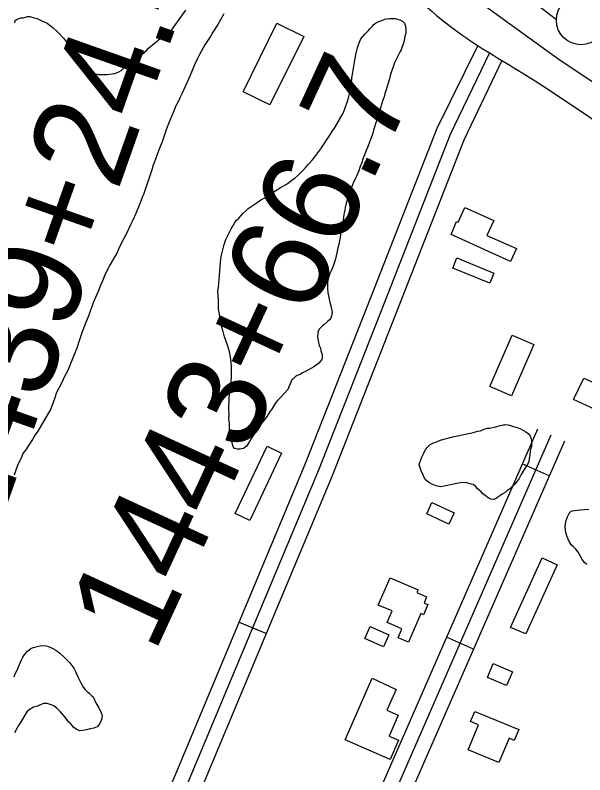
# Model space of a CAD drawing. Extents: x 3887375 to 3925618, y 296674 to 322633.
# Drawn here: x 3891643 to 3892222, y 311417 to 312189 of the extents above; entities that cross this region are included whole.
import ezdxf

# ---------------------------------------------------------------- set-up
doc = ezdxf.new("R2010")
doc.units = 0
for name, color, linetype in [('V-BLDG-OTLN', 7, 'Continuous'), ('V-LEVE-TOET', 7, 'Continuous'), ('V-RIVR-EDGE', 7, 'Continuous'), ('V-ROAD-CNTR', 7, 'Continuous'), ('V-RRAP-FSHR', 7, 'Continuous'), ('V-SITE-VEGE', 7, 'Continuous'), ('V-SURV-IDEN', 7, 'Continuous'), ('V-SURV-LINE', 7, 'Continuous')]:
    doc.layers.add(name, color=color, linetype=linetype)

msp = doc.modelspace()

# ---------------------------------------------------------------- linework, layer by layer
at = {"layer": 'V-BLDG-OTLN'}
for points in [[(3891902.41, 312097.6), (3891875.15, 312110.99), (3891909.54, 312180.64), (3891936.77, 312167.2)], [(3892086.66, 311965.84), (3892091.99, 311979.05), (3892093.66, 311978.3), (3892100.46, 311993.38), (3892129.87, 311980.1), (3892123.03, 311964.96), (3892152.89, 311951.48), (3892147.06, 311938.57)], [(3892092.51, 311942.05), (3892130.07, 311926.68), (3892125.81, 311916.29), (3892088.41, 311931.6)], [(3892148.62, 311863.4), (3892170.71, 311853.97), (3892148.11, 311801.7), (3892126.05, 311811.24)], [(3892221.56, 311819.8), (3892247.45, 311807.8), (3892237.28, 311785.86), (3892210.85, 311798.12)], [(3891899.55, 311750.87), (3891914.06, 311743.49), (3891881.89, 311675.27), (3891867.17, 311682.22)], [(3892067.12, 311693.45), (3892089.7, 311683.01), (3892084.36, 311671.47), (3892061.71, 311681.94)], [(3892147.02, 311566.42), (3892179.21, 311637.1), (3892194.4, 311630.18), (3892162.49, 311560.12)], [(3892024.54, 311617.05), (3892052.91, 311604.81), (3892051.63, 311601.83), (3892061.7, 311597.48), (3892059.01, 311591.25), (3892062.77, 311589.62), (3892058.35, 311579.37), (3892055.71, 311580.51), (3892043.16, 311551.43), (3892032.63, 311555.97), (3892036.59, 311565.15), (3892021.61, 311571.62), (3892026.6, 311583.18), (3892012.56, 311589.23)], [(3892004.29, 311567.43), (3892023.14, 311558.95), (3892017.7, 311546.85), (3891998.86, 311555.33)], [(3892129.22, 311529.73), (3892149, 311521.26), (3892143.03, 311507.34), (3892123.58, 311515.67)], [(3892006.17, 311515), (3892030.58, 311503.54), (3892021.31, 311482.29), (3892032.8, 311477.28), (3892023.54, 311456.06), (3892032.98, 311451.95), (3892024.46, 311432.39), (3891978.82, 311452.3)], [(3892110.7, 311481.05), (3892155.37, 311462.57), (3892150.83, 311451.61), (3892145.46, 311453.83), (3892135.23, 311429.12), (3892103.97, 311442.06), (3892114.44, 311467.37), (3892106.39, 311470.7)]]:
    msp.add_lwpolyline(points, close=True, dxfattribs=at)
at = {"layer": 'V-LEVE-TOET'}
msp.add_lwpolyline([(3891470.84, 312662.89), (3891560.54, 312610.95), (3891672.72, 312538.88), (3891789.15, 312457.06), (3891908.44, 312364.28), (3891989.87, 312296.2), (3892058.03, 312243.98), (3892194.92, 312144.74), (3892319.54, 312061.78), (3892457.42, 311963.54), (3892587.1, 311868.44), (3892728.16, 311772.22), (3892868.41, 311677.19), (3892941.75, 311626.8), (3893041.76, 311554.85), (3893157.21, 311470.62), (3893331.95, 311347.69), (3893386.65, 311309.75), (3893477.31, 311234.74), (3893652.21, 311086.68), (3893804.29, 310952.63), (3893919.11, 310842.87), (3893996.64, 310761.99)], dxfattribs=at)
at = {"layer": 'V-RIVR-EDGE'}
msp.add_spline([(3891467.98, 312833.96), (3891486.98, 312822.05), (3891534.01, 312792.8), (3891594.13, 312753.8), (3891650.38, 312718.69), (3891687.23, 312694.81), (3891715.84, 312678.71), (3891775.97, 312641.17), (3891829.3, 312607.04), (3891872.45, 312576.34), (3891897.65, 312554.91), (3891920.44, 312540.28), (3891948.54, 312515.93), (3892002.83, 312474.52), (3892042.08, 312440.43), (3892073.59, 312415.58), (3892102.19, 312395.6), (3892133.21, 312371.24), (3892200.11, 312321.54), (3892242.77, 312292.79), (3892291.73, 312258.18), (3892341.66, 312219.21), (3892369.29, 312198.26), (3892390.13, 312181.21), (3892413.88, 312163.18), (3892453.63, 312136.38), (3892487.09, 312113.47), (3892521.99, 312087.64), (3892554.96, 312065.22), (3892591.32, 312042.31), (3892628.16, 312015.99), (3892662.1, 311994.06), (3892686.84, 311979.91), (3892764.9, 311931.15), (3892805.14, 311902.89), (3892836.17, 311880.47), (3892877.86, 311852.69), (3892924.41, 311821.49), (3892965.13, 311793.23), (3893024.77, 311754.23), (3893079.06, 311715.73), (3893108.15, 311694.29), (3893146.45, 311668.94), (3893184.74, 311638.74), (3893227.88, 311606.09), (3893285.08, 311562.73), (3893338.89, 311523.75), (3893381.55, 311493.05), (3893441.66, 311449.68), (3893482.38, 311419.95), (3893505.63, 311395.61), (3893524.53, 311379.05), (3893555.07, 311358.1), (3893588.51, 311330.33), (3893620.5, 311305.49), (3893676.23, 311256.3), (3893730.02, 311212.46), (3893771.69, 311174.96), (3893804.16, 311145.26), (3893965.04, 311005.48), (3893991.69, 310979.19), (3894015.41, 310950.48), (3894041.09, 310924.19), (3894068.7, 310897.9)], degree=3, dxfattribs=at)
at = {"layer": 'V-ROAD-CNTR'}
for p, q in [((3892186.32, 311720.71), (3892158.83, 311732.72)), ((3891871.15, 311571.72), (3891898.83, 311560.14)), ((3892109.33, 311544.46), (3892081.84, 311556.47))]:
    msp.add_line(p, q, dxfattribs=at)
for points in [[(3891686.27, 311129.7), (3891938.31, 311732.3), (3892005.6, 311903.59), (3892072.28, 312073.95), (3892114.12, 312158.17)], [(3891700.11, 311123.91), (3891952.22, 311726.66), (3892019.56, 311898.11), (3892086.04, 312067.96), (3892125.89, 312150.89)], [(3891713.95, 311118.12), (3891966.12, 311721.03), (3892033.53, 311892.64), (3892099.8, 312061.97), (3892138.54, 312143.08)], [(3892174.23, 311767.97), (3892020.24, 311415.46), (3891893.42, 311123.43), (3891858.77, 311046.87)], [(3892187.97, 311761.96), (3892034, 311409.47), (3891907.14, 311117.35), (3891872.44, 311040.68)], [(3892201.72, 311755.96), (3892047.75, 311403.48), (3891920.85, 311111.27), (3891886.11, 311034.5)]]:
    msp.add_lwpolyline(points, dxfattribs=at)
for points in [[(3891930.71, 312305.17), (3892016.94, 312237.42), (3892090.97, 312173.45), (3892154.3, 312132.93), (3892292.49, 312039.88), (3892440.64, 311937.24), (3892591.28, 311832.93), (3892771.43, 311706.32), (3892952.89, 311582.91), (3893068.84, 311500.71)], [(3892116.12, 310915.27), (3892145.02, 310967.97), (3892195.12, 311066.62), (3892242.62, 311173.92), (3892293.84, 311292.92), (3892337.19, 311399.23), (3892384.83, 311516.5)]]:
    msp.add_spline(points, degree=3, dxfattribs=at)
at = {"layer": 'V-RRAP-FSHR'}
msp.add_spline([(3893114.78, 311697.57), (3893051.01, 311741.57), (3892934.52, 311826.93), (3892830.41, 311900.74), (3892716.58, 311970.79), (3892537.08, 312088.03), (3892396.96, 312185.57), (3892228.16, 312311.27), (3892082.04, 312421.65), (3891952.19, 312519.08)], degree=3, dxfattribs=at)
at = {"layer": 'V-SITE-VEGE'}
for p, q in [((3891801.48, 312172.66), (3891816.94, 312193.9)), ((3891645.23, 312184.85), (3891649.18, 312185.93)), ((3891649.18, 312185.93), (3891651.82, 312186.21)), ((3891651.82, 312186.21), (3891656.04, 312187.3)), ((3891656.04, 312187.3), (3891658.42, 312187.31)), ((3891658.42, 312187.31), (3891662.66, 312186.02)), ((3891662.66, 312186.02), (3891665.57, 312185.51)), ((3891665.57, 312185.51), (3891670.61, 312182.9)), ((3891855.54, 312190.19), (3891849.27, 312179.31)), ((3891642.87, 312181.13), (3891643.38, 312183.51)), ((3891643.38, 312183.51), (3891645.23, 312184.85)), ((3891670.61, 312182.9), (3891672.73, 312182.12)), ((3891672.73, 312182.12), (3891675.91, 312180.55)), ((3891675.91, 312180.55), (3891682.02, 312175.84)), ((3891849.27, 312179.31), (3891844.3, 312171.35)), ((3891682.02, 312175.84), (3891684.94, 312173.21)), ((3891684.94, 312173.21), (3891687.33, 312170.85)), ((3891687.33, 312170.85), (3891692.39, 312165.34)), ((3891797.54, 312169.72), (3891801.48, 312172.66)), ((3891844.3, 312171.35), (3891842.21, 312167.64)), ((3891692.39, 312165.34), (3891699.59, 312155.87)), ((3891778.87, 312155.07), (3891792.8, 312166.79)), ((3891792.8, 312166.79), (3891794.64, 312168.12)), ((3891794.64, 312168.12), (3891797.54, 312169.72)), ((3891842.21, 312167.64), (3891836.19, 312158.61)), ((3891699.59, 312155.87), (3891703.05, 312151.66)), ((3891777.03, 312152.94), (3891778.87, 312155.07)), ((3891836.19, 312158.61), (3891830.71, 312148.8)), ((3891703.05, 312151.66), (3891712.63, 312140.89)), ((3891765.47, 312144.14), (3891772.57, 312149.21)), ((3891772.57, 312149.21), (3891777.03, 312152.94)), ((3891830.71, 312148.8), (3891828.62, 312144.82)), ((3891712.63, 312140.89), (3891714.5, 312137.99)), ((3891755.73, 312136.94), (3891762.84, 312141.75)), ((3891762.84, 312141.75), (3891765.47, 312144.14)), ((3891828.62, 312144.82), (3891825.76, 312138.2)), ((3891714.5, 312137.99), (3891717.7, 312134.32)), ((3891717.7, 312134.32), (3891721.69, 312130.38)), ((3891748.64, 312131.08), (3891751.01, 312132.69)), ((3891751.01, 312132.69), (3891752.58, 312134.02)), ((3891752.58, 312134.02), (3891755.73, 312136.94)), ((3891825.76, 312138.2), (3891821.07, 312126.8)), ((3891721.69, 312130.38), (3891724.87, 312129.08)), ((3891724.87, 312129.08), (3891728.57, 312128.57)), ((3891728.57, 312128.57), (3891731.22, 312128.33)), ((3891731.22, 312128.33), (3891737.03, 312128.36)), ((3891737.03, 312128.36), (3891739.41, 312128.65)), ((3891739.41, 312128.65), (3891744.69, 312129.47)), ((3891744.69, 312129.47), (3891748.64, 312131.08)), ((3891821.07, 312126.8), (3891816.65, 312116.99)), ((3891816.65, 312116.99), (3891812.74, 312108.78)), ((3891812.74, 312108.78), (3891811.17, 312105.33)), ((3891809.87, 312102.15), (3891806.74, 312096.58)), ((3891811.17, 312105.33), (3891809.87, 312102.15)), ((3891806.74, 312096.58), (3891804.92, 312092.34)), ((3891804.92, 312092.34), (3891798.94, 312077.5)), ((3891798.94, 312077.5), (3891796.85, 312072.2)), ((3891796.85, 312072.2), (3891792.71, 312060.02)), ((3891792.71, 312060.02), (3891789.07, 312051.01)), ((3891789.07, 312051.01), (3891787.25, 312045.98)), ((3891784.65, 312038.83), (3891783.35, 312035.65)), ((3891786.21, 312043.6), (3891784.65, 312038.83)), ((3891787.25, 312045.98), (3891786.21, 312043.6)), ((3891782.58, 312032.47), (3891779.73, 312023.47)), ((3891783.35, 312035.65), (3891782.58, 312032.47)), ((3891779.73, 312023.47), (3891773.77, 312006.52)), ((3891772.72, 312004.4), (3891770.38, 311998.04)), ((3891773.77, 312006.52), (3891772.72, 312004.4)), ((3891770.38, 311998.04), (3891765.96, 311987.17)), ((3891765.96, 311987.17), (3891762.84, 311980.28)), ((3891762.84, 311980.28), (3891760.49, 311975.51)), ((3891760.49, 311975.51), (3891756.84, 311967.56)), ((3891753.97, 311961.73), (3891749.54, 311953.24)), ((3891756.84, 311967.56), (3891753.97, 311961.73)), ((3891746.93, 311947.67), (3891739.88, 311935.21)), ((3891749.54, 311953.24), (3891746.93, 311947.67)), ((3891739.88, 311935.21), (3891736.22, 311928.31)), ((3891734.14, 311923.81), (3891732.32, 311919.3)), ((3891736.22, 311928.31), (3891734.14, 311923.81)), ((3891732.32, 311919.3), (3891729.71, 311913.47)), ((3891728.42, 311909.76), (3891722.69, 311896.25)), ((3891729.71, 311913.47), (3891728.42, 311909.76)), ((3891722.69, 311896.25), (3891717.5, 311882.21)), ((3891717.5, 311882.21), (3891714.9, 311875.85)), ((3891713.6, 311871.88), (3891711.52, 311866.84)), ((3891714.9, 311875.85), (3891713.6, 311871.88)), ((3891711.52, 311866.84), (3891708.15, 311856.78)), ((3891708.15, 311856.78), (3891706.08, 311850.16)), ((3891704.25, 311846.18), (3891696.45, 311827.1)), ((3891706.08, 311850.16), (3891704.25, 311846.18)), ((3891696.45, 311827.1), (3891693.84, 311822.06)), ((3891690.45, 311814.91), (3891685.5, 311805.1)), ((3891693.84, 311822.06), (3891690.45, 311814.91)), ((3891685.5, 311805.1), (3891683.42, 311798.74)), ((3891681.86, 311795.03), (3891679.52, 311788.68)), ((3891683.42, 311798.74), (3891681.86, 311795.03)), ((3891679.52, 311788.68), (3891666.46, 311765.86)), ((3891663.58, 311762.14), (3891660.96, 311757.63)), ((3891666.46, 311765.86), (3891663.58, 311762.14)), ((3891660.96, 311757.63), (3891657.04, 311751.53)), ((3891654.95, 311748.08), (3891652.59, 311744.89)), ((3891657.04, 311751.53), (3891654.95, 311748.08)), ((3891649.72, 311739.33), (3891648.42, 311736.94)), ((3891651.28, 311743.3), (3891649.72, 311739.33)), ((3891652.59, 311744.89), (3891651.28, 311743.3)), ((3891645.81, 311731.11), (3891644.51, 311727.4)), ((3891648.42, 311736.94), (3891645.81, 311731.11)), ((3891644.51, 311727.4), (3891642.18, 311721.31))]:
    msp.add_line(p, q, dxfattribs=at)
for points in [[(3891861.49, 311765.02), (3891861.21, 311767.93), (3891861.17, 311774.53), (3891860.62, 311777.7), (3891860.84, 311783.52), (3891860.55, 311788.27), (3891861, 311799.9), (3891861.49, 311805.46), (3891862.76, 311813.39), (3891863.01, 311816.3), (3891863.24, 311821.06), (3891863.18, 311830.57), (3891862.88, 311836.12), (3891862.04, 311843.51), (3891861.22, 311846.94), (3891859.6, 311852.22), (3891857.45, 311858.02), (3891856.1, 311861.97), (3891854.75, 311867.25), (3891852.85, 311873.84), (3891850.93, 311884.93), (3891850.1, 311890.21), (3891850.05, 311898.67), (3891849.46, 311908.44), (3891849.96, 311912.14), (3891850.94, 311924.3), (3891852.17, 311937.79), (3891852.93, 311943.35), (3891855.76, 311955.52), (3891857.57, 311960.82), (3891863.05, 311971.69), (3891865.15, 311974.87), (3891866.45, 311977.26), (3891868.54, 311980.44), (3891870.65, 311982.31), (3891873, 311985.23), (3891874.84, 311987.09), (3891877.99, 311989.75), (3891880.36, 311992.15), (3891882.2, 311993.75), (3891890.36, 311999.09), (3891893.25, 312001.22), (3891896.41, 312002.83), (3891901.68, 312005.77), (3891905.09, 312008.43), (3891910.09, 312011.64), (3891913.25, 312013.51), (3891918.26, 312016.18), (3891921.41, 312018.31), (3891925.1, 312021.25), (3891927.72, 312023.11), (3891930.88, 312025.78), (3891936.65, 312031.63), (3891939.28, 312034.55), (3891941.64, 312037.48), (3891945.57, 312041.73), (3891947.93, 312044.65), (3891954.22, 312052.89), (3891957.62, 312057.93), (3891959.98, 312061.64), (3891963.11, 312066.95), (3891966.25, 312071.46), (3891968.09, 312073.85), (3891976.97, 312089.23), (3891978.27, 312092.42), (3891981.9, 312103.28), (3891983.96, 312111.48), (3891985.23, 312119.95), (3891985.73, 312124.44), (3891987.76, 312136.88), (3891988.26, 312140.84), (3891989.03, 312144.81), (3891989.53, 312148.52), (3891990.83, 312153.02), (3891991.34, 312155.66), (3891992.63, 312159.63), (3891994.71, 312164.67), (3891999.17, 312169.72), (3892002.59, 312173.18), (3892003.9, 312175.04), (3892006.52, 312177.43), (3892008.1, 312179.29), (3892009.67, 312180.62), (3892012.31, 312181.96), (3892016.79, 312183.84), (3892020.48, 312185.18), (3892023.91, 312185.47), (3892026.29, 312185.49), (3892029.73, 312185.25), (3892034.49, 312183.96), (3892037.14, 312182.65), (3892039.01, 312180.55), (3892040.08, 312177.65), (3892040.37, 312174.48), (3892040.4, 312169.99), (3892039.62, 312167.6), (3892039.11, 312164.96), (3892038.86, 312162.58), (3892037.83, 312159.14), (3892036.53, 312155.96), (3892035.75, 312153.57)], [(3892035.75, 312153.57), (3892034.7, 312151.72), (3892032.88, 312147.74), (3892028.96, 312140.32), (3892024.56, 312127.34)], [(3892024.56, 312127.34), (3892023.79, 312123.9), (3892020.17, 312111.72), (3892019.13, 312108.8), (3892018.36, 312105.63), (3892017.58, 312103.24), (3892016.8, 312101.39), (3892014.73, 312094.51), (3892013.43, 312090.53), (3892011.88, 312086.29), (3892011.1, 312083.65), (3892010.33, 312080.21), (3892007.74, 312072), (3892006.97, 312068.82), (3892006.19, 312066.97), (3892001.51, 312054.25), (3892000.21, 312051.34), (3891997.09, 312043.39), (3891995.54, 312038.09), (3891994.24, 312034.91), (3891992.68, 312030.41), (3891990.6, 312025.9), (3891989.3, 312022.72), (3891987.21, 312019.01), (3891985.13, 312013.71), (3891984.09, 312011.59), (3891983.31, 312008.68), (3891982.27, 312006.03), (3891981.76, 312003.91), (3891979.95, 311997.56), (3891978.92, 311993.32), (3891978.41, 311990.68), (3891977.38, 311986.44), (3891977.14, 311983.27), (3891976.38, 311977.98), (3891974.59, 311968.98), (3891974.08, 311965.02), (3891972.3, 311955.75), (3891971.53, 311952.31), (3891970.24, 311947.28), (3891969.73, 311944.11), (3891968.7, 311939.61), (3891966.63, 311933.52), (3891964.54, 311928.75), (3891963.24, 311926.36), (3891962.2, 311923.18), (3891961.17, 311919.48), (3891960.92, 311916.57), (3891960.96, 311911.02), (3891961.25, 311906.79), (3891962.34, 311901.78), (3891962.89, 311898.35), (3891964.25, 311893.34), (3891965.61, 311887), (3891965.11, 311883.03), (3891964.33, 311880.91), (3891963.02, 311879.05), (3891960.39, 311876.92), (3891957.24, 311874), (3891955.4, 311872.66), (3891952.51, 311869.74), (3891950.95, 311866.55), (3891950.72, 311861.01), (3891951.27, 311857.84), (3891952.35, 311853.09), (3891953.69, 311850.19), (3891954.24, 311847.55), (3891955.32, 311843.86), (3891955.6, 311841.48), (3891955.09, 311838.84), (3891952.21, 311835.12), (3891946.95, 311831.38), (3891941.42, 311828.44), (3891938.52, 311826.57), (3891935.62, 311825.23), (3891932.99, 311823.63), (3891930.09, 311822.55), (3891927.99, 311821.22), (3891924.57, 311818.29), (3891921.71, 311811.13), (3891920.41, 311808.22), (3891913.06, 311800.24), (3891910.43, 311797.58), (3891908.08, 311794.66), (3891904.15, 311788.29), (3891902.58, 311786.17), (3891898.39, 311779.8), (3891895.77, 311776.61), (3891892.11, 311771.57), (3891883.21, 311758.56), (3891881.12, 311754.85), (3891878.5, 311750.86), (3891875.35, 311748.2), (3891872.18, 311747.65), (3891869.27, 311747.63), (3891866.36, 311748.4), (3891865.03, 311750.24), (3891863.95, 311753.68), (3891863.66, 311756.58), (3891862.04, 311762.38), (3891861.49, 311765.02)], [(3892224.42, 311630.51), (3892222.29, 311632.61), (3892219.63, 311635.5), (3892217.21, 311640.76), (3892215.88, 311642.87), (3892213.22, 311646.02), (3892210.82, 311648.39), (3892208.96, 311649.96), (3892206.56, 311653.91), (3892204.68, 311658.39), (3892203.06, 311662.87), (3892202.79, 311664.98), (3892202.49, 311669.47), (3892203.51, 311675.29), (3892204.81, 311679), (3892206.11, 311681.65), (3892207.42, 311683.78), (3892209.53, 311684.85), (3892217.71, 311685.96), (3892226.69, 311686.81)], [(3891642.2, 311516.24), (3891643.49, 311519.41), (3891645.06, 311522.33), (3891646.62, 311526.57), (3891649.75, 311533.46), (3891651.05, 311536.11), (3891652.62, 311538.24), (3891656.03, 311542.23), (3891659.45, 311545.15), (3891661.82, 311546.23), (3891665.78, 311547.04), (3891670.26, 311548.13), (3891674.76, 311547.63), (3891677.4, 311547.12), (3891682.44, 311544.78), (3891684.83, 311543.21), (3891688.28, 311540.59), (3891693.87, 311535.6), (3891695.73, 311533.5), (3891698.92, 311530.35), (3891702.92, 311525.09), (3891704.79, 311521.67), (3891707.47, 311515.61), (3891710.42, 311509.55), (3891712.56, 311505.86), (3891714.69, 311503.23), (3891716.28, 311501.66), (3891718.68, 311499.56), (3891720.81, 311497.19), (3891722.66, 311495.89), (3891725.62, 311489.03), (3891728.02, 311485.35), (3891730.96, 311479.82), (3891731.77, 311476.92), (3891731.53, 311474.01), (3891730.49, 311470.83), (3891728.66, 311467.65), (3891726.56, 311465.52), (3891723.4, 311464.18), (3891719.71, 311463.36), (3891715.75, 311462.28), (3891712.32, 311461.73), (3891709.15, 311461.44), (3891705.44, 311463), (3891703.05, 311464.84), (3891699.85, 311468.52), (3891697.73, 311470.62), (3891693.73, 311475.61), (3891689.47, 311480.6), (3891687.61, 311482.44), (3891685.74, 311484.55), (3891682.56, 311486.9), (3891679.91, 311487.94), (3891675.93, 311489.24), (3891672.23, 311489.21), (3891665.12, 311486.26), (3891661.95, 311485.45), (3891657.74, 311482.78), (3891655.38, 311480.65), (3891653.02, 311477.46), (3891649.89, 311471.62), (3891646.75, 311466.85), (3891645.18, 311463.67), (3891642.83, 311459.42)]]:
    msp.add_lwpolyline(points, dxfattribs=at)
msp.add_lwpolyline([(3892165.6, 311735.04), (3892164.29, 311732.12), (3892161.42, 311727.87), (3892159.85, 311725.22), (3892157.75, 311722.03), (3892155.67, 311717.79), (3892153.83, 311715.14), (3892151.21, 311712.22), (3892147.8, 311709.02), (3892145.96, 311707.16), (3892143.33, 311705.29), (3892141.49, 311703.69), (3892139.12, 311702.36), (3892137.02, 311700.76), (3892134.12, 311698.89), (3892132.28, 311697.55), (3892129.91, 311696.48), (3892127, 311696.99), (3892124.35, 311698.3), (3892122.49, 311699.6), (3892118.5, 311702.75), (3892117.17, 311704.33), (3892113.18, 311707.74), (3892111.59, 311709.58), (3892108.93, 311711.67), (3892106.81, 311712.19), (3892102.58, 311713.48), (3892098.08, 311713.72), (3892092.27, 311712.89), (3892085.94, 311711.52), (3892082.78, 311710.71), (3892079.34, 311710.16), (3892075.91, 311709.34), (3892071.41, 311710.37), (3892066.12, 311712.45), (3892063.99, 311713.76), (3892060.27, 311716.9), (3892058.67, 311719.8), (3892055.99, 311725.6), (3892054.64, 311729.55), (3892054.09, 311732.19), (3892056.43, 311738.81), (3892058.52, 311743.05), (3892059.56, 311745.44), (3892060.86, 311747.56), (3892062.7, 311749.69), (3892065.33, 311752.35), (3892068.75, 311754.22), (3892070.86, 311754.76), (3892074.02, 311756.1), (3892076.92, 311757.18), (3892080.35, 311758), (3892089.58, 311760.7), (3892093.54, 311761.25), (3892104.1, 311763.7), (3892106.74, 311763.98), (3892113.6, 311765.88), (3892116.5, 311766.42), (3892118.35, 311767.23), (3892121.25, 311768.3), (3892123.62, 311768.85), (3892125.73, 311769.13), (3892132.07, 311770.49), (3892136.55, 311771.84), (3892138.66, 311772.12), (3892140.77, 311772.66), (3892144.47, 311772.42), (3892150.03, 311770.61), (3892154.8, 311769.32), (3892157.72, 311768.02), (3892162.49, 311765.4), (3892164.88, 311763.57), (3892167.01, 311760.94), (3892167.82, 311758.57), (3892168.37, 311755.93), (3892168.38, 311753.29), (3892168.14, 311750.38), (3892167.36, 311747.73)], close=True, dxfattribs=at)
at = {"layer": 'V-SURV-LINE'}
msp.add_lwpolyline([(3892193.59, 312184.02), (3891874.78, 312429.29)], dxfattribs=at)
msp.add_circle((3892218.58, 312183.72), 25, dxfattribs=at)

# ---------------------------------------------------------------- texts
at = {"layer": 'V-SURV-IDEN'}
for s, rotation, p in [('1439+24.4', 70.53545, (3891622.22, 311654.59)), ('1443+66.7', 65.21466, (3891784.59, 311538.77))]:
    msp.add_text(s, height=100, rotation=rotation, dxfattribs=at).set_placement(p)

doc.saveas('drawing.dxf')
